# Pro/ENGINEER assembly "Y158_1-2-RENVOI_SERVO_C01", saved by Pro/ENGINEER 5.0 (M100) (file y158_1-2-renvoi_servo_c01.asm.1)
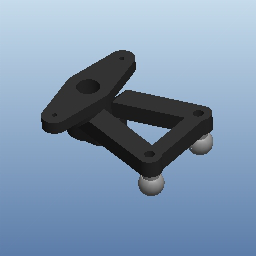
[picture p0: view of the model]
Units: millimeter Newton Second (mmNs); MM, TONNE, HOURS

Other components: 80151502-SAUVE_SERVO_C01, 80151501-SAUVE_SERVO_C01, 80025000-ROTULE_STD, 80025000-ROTULE_STD

Other named items: A-DROITE, A-DESSUS, A-FACE, A-R0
